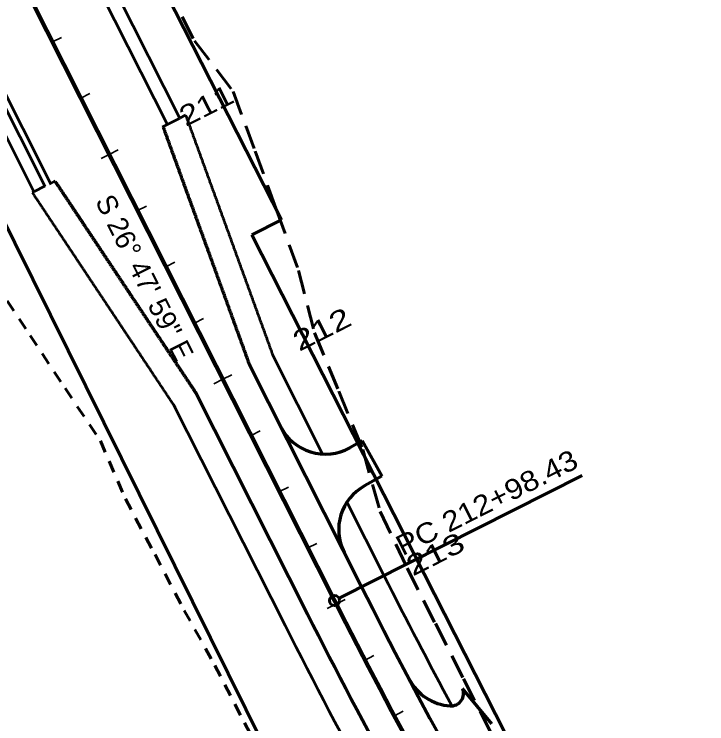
# Model space of a CAD drawing. Extents: x 2717836 to 2719883, y 337327 to 339813.
# Drawn here: x 2718519.7 to 2718794.7, y 338625.8 to 338907.4 of the extents above; entities that cross this region are included whole.
import ezdxf
from ezdxf.enums import TextEntityAlignment as Align

# ---------------------------------------------------------------- set-up
doc = ezdxf.new("R2010")
doc.units = 0
doc.header["$LTSCALE"] = 3.2
doc.linetypes.add('MEDIUM_DASHED', pattern=[4.5, 3, -1.5])
doc.linetypes.add('SHORT_DASHED', pattern=[2.7, 1.5, -1.2])
for name, color, linetype, lineweight in [('1', 7, 'Continuous', 106), ('22', 7, 'SHORT_DASHED', 60), ('23', 7, 'Continuous', 70), ('3', 7, 'Continuous', 70), ('31', 7, 'Continuous', 35), ('4', 7, 'Continuous', 53), ('6', 7, 'Continuous', 53), ('7', 7, 'Continuous', 53)]:
    doc.layers.add(name, color=color, linetype=linetype, lineweight=lineweight)

msp = doc.modelspace()

# ---------------------------------------------------------------- linework, layer by layer
at = {"layer": '1'}
msp.add_line((2718525.819, 338914.331), (2718646.872, 338674.684), dxfattribs=at)
msp.add_arc((2720744.453, 339734.238), 2350, 206.79977, 222.16044, dxfattribs=at)
at = {"layer": '22', "linetype": 'MEDIUM_DASHED'}
for p, q in [((2718579.936, 338919.199), (2718591.209, 338896.885)), ((2718591.209, 338896.885), (2718606.68, 338876.691)), ((2718606.68, 338876.691), (2718615.357, 338853.066)), ((2718615.357, 338853.066), (2718623.949, 338829.398)), ((2718623.949, 338829.398), (2718632.545, 338805.731)), ((2718632.545, 338805.731), (2718638.962, 338780.964)), ((2718638.962, 338780.964), (2718648.549, 338757.798)), ((2718648.549, 338757.798), (2718658.062, 338734.595)), ((2718658.062, 338734.595), (2718664.941, 338710.061)), ((2718664.941, 338710.061), (2718675.732, 338687.528)), ((2718675.732, 338687.528), (2718686.922, 338665.547)), ((2718686.922, 338665.547), (2718698.114, 338643.563)), ((2718698.114, 338643.563), (2718709.311, 338621.571))]:
    msp.add_line(p, q, dxfattribs=at)
at = {"layer": '22'}
for p, q in [((2718512.15, 338800.933), (2718525.967, 338779.904)), ((2718525.967, 338779.904), (2718539.924, 338758.946)), ((2718539.924, 338758.946), (2718553.951, 338738.023)), ((2718553.951, 338738.023), (2718563.831, 338715.005)), ((2718563.831, 338715.005), (2718575.588, 338692.935)), ((2718575.588, 338692.935), (2718587.141, 338670.762)), ((2718587.141, 338670.762), (2718599.4, 338648.906)), ((2718599.4, 338648.906), (2718611.069, 338626.149)), ((2718611.069, 338626.149), (2718623.203, 338603.636))]:
    msp.add_line(p, q, dxfattribs=at)
at = {"layer": '23'}
for q in [(2718555.033, 338964.813), (2718613.983, 338819.832)]:
    msp.add_line((2718625.785, 338825.842), q, dxfattribs=at)
for points in [[(2718625.836, 338603.023), (2718449.262, 338959.135), (2718424.429, 339000.578), (2718281.942, 339176.113)], [(2718753.327, 338557.168), (2718739.901, 338550.479), (2718714.737, 338599.901), (2718722.9, 338605.899), (2718678.474, 338693.162), (2718613.983, 338819.832)]]:
    msp.add_lwpolyline(points, dxfattribs=at)
at = {"layer": '3'}
for p, q in [((2718613.203, 338767.953), (2718657.583, 338680.095)), ((2718591.781, 338757.132), (2718636.161, 338669.274)), ((2718657.858, 338738.049), (2718652.963, 338735.332)), ((2718657.858, 338738.049), (2718665.624, 338724.06)), ((2718665.624, 338724.06), (2718658.816, 338720.28)), ((2718709.309, 338625.768), (2718697.745, 338639.806))]:
    msp.add_line(p, q, dxfattribs=at)
for centre, radius, start, end in [((2718643.255, 338752.818), 20, 206.79977, 299.03779), ((2718668.523, 338702.794), 20, 119.03779, 206.79977), ((2720744.453, 339734.238), 2338, 206.79977, 222.16044), ((2720744.453, 339734.238), 2362, 206.79977, 214.15238), ((2718694.161, 338652.837), 20, 207.80885, 266.07563), ((2718693.135, 338637.872), 5, 266.07563, 22.75978)]:
    msp.add_arc(centre, radius, start, end, dxfattribs=at)
for points in [[(2718578.827, 338862.622), (2718579.061, 338861.978), (2718579.291, 338861.344), (2718579.525, 338860.7), (2718579.755, 338860.066), (2718579.989, 338859.422), (2718580.219, 338858.788), (2718580.453, 338858.144), (2718580.687, 338857.5), (2718580.917, 338856.866), (2718581.151, 338856.222), (2718581.381, 338855.588), (2718581.615, 338854.944), (2718581.845, 338854.31), (2718582.079, 338853.666), (2718582.313, 338853.023), (2718582.543, 338852.388), (2718582.777, 338851.745), (2718583.007, 338851.11), (2718583.241, 338850.466), (2718583.471, 338849.832), (2718583.705, 338849.188), (2718583.935, 338848.554), (2718584.169, 338847.91), (2718584.403, 338847.267), (2718584.633, 338846.632), (2718584.867, 338845.989), (2718585.097, 338845.354), (2718585.331, 338844.71), (2718585.561, 338844.076), (2718585.795, 338843.432), (2718586.029, 338842.789), (2718586.259, 338842.154), (2718586.493, 338841.511), (2718586.723, 338840.876), (2718586.957, 338840.233), (2718587.187, 338839.598), (2718587.421, 338838.955), (2718587.655, 338838.311), (2718587.885, 338837.676), (2718588.119, 338837.033), (2718588.349, 338836.398), (2718588.583, 338835.755), (2718588.813, 338835.12), (2718589.047, 338834.477), (2718589.281, 338833.833), (2718589.511, 338833.199), (2718589.745, 338832.555), (2718589.975, 338831.92), (2718590.209, 338831.277), (2718590.439, 338830.642), (2718590.673, 338829.999), (2718590.907, 338829.355), (2718591.137, 338828.721), (2718591.371, 338828.077), (2718591.601, 338827.443), (2718591.835, 338826.799), (2718592.065, 338826.165), (2718592.299, 338825.521), (2718592.529, 338824.886), (2718592.763, 338824.243), (2718592.997, 338823.599), (2718593.227, 338822.965), (2718593.461, 338822.321), (2718593.691, 338821.687), (2718593.925, 338821.043), (2718594.155, 338820.409), (2718594.389, 338819.765), (2718594.623, 338819.122), (2718594.853, 338818.487), (2718595.087, 338817.843), (2718595.317, 338817.209), (2718595.551, 338816.565), (2718595.781, 338815.931), (2718596.015, 338815.287)], [(2718535.983, 338840.98), (2718536.362, 338840.409), (2718536.736, 338839.848), (2718537.115, 338839.278), (2718537.49, 338838.716), (2718537.868, 338838.146), (2718538.243, 338837.584), (2718538.622, 338837.014), (2718539.001, 338836.443), (2718539.375, 338835.882), (2718539.754, 338835.312), (2718540.129, 338834.75), (2718540.508, 338834.18), (2718540.882, 338833.618), (2718541.261, 338833.048), (2718541.64, 338832.477), (2718542.015, 338831.916), (2718542.394, 338831.346), (2718542.768, 338830.784), (2718543.147, 338830.214), (2718543.521, 338829.652), (2718543.9, 338829.082), (2718544.275, 338828.52), (2718544.654, 338827.95), (2718545.033, 338827.379), (2718545.407, 338826.818), (2718545.786, 338826.248), (2718546.161, 338825.686), (2718546.54, 338825.116), (2718546.914, 338824.554), (2718547.293, 338823.984), (2718547.672, 338823.413), (2718548.046, 338822.852), (2718548.425, 338822.282), (2718548.8, 338821.72), (2718549.179, 338821.15), (2718549.553, 338820.588), (2718549.932, 338820.018), (2718550.311, 338819.447), (2718550.686, 338818.886), (2718551.065, 338818.316), (2718551.439, 338817.754), (2718551.818, 338817.184), (2718552.193, 338816.622), (2718552.572, 338816.052), (2718552.95, 338815.481), (2718553.325, 338814.92), (2718553.704, 338814.349), (2718554.078, 338813.788), (2718554.457, 338813.218), (2718554.832, 338812.656), (2718555.211, 338812.086), (2718555.59, 338811.515), (2718555.964, 338810.954), (2718556.343, 338810.383), (2718556.718, 338809.822), (2718557.097, 338809.252), (2718557.471, 338808.69), (2718557.85, 338808.12), (2718558.224, 338807.558), (2718558.603, 338806.988), (2718558.982, 338806.417), (2718559.357, 338805.856), (2718559.736, 338805.286), (2718560.11, 338804.724), (2718560.489, 338804.154), (2718560.864, 338803.592), (2718561.243, 338803.022), (2718561.622, 338802.451), (2718561.996, 338801.89), (2718562.375, 338801.319), (2718562.749, 338800.758), (2718563.128, 338800.188), (2718563.503, 338799.626), (2718563.882, 338799.056)], [(2718596.015, 338815.287), (2718596.249, 338814.644), (2718596.479, 338814.009), (2718596.713, 338813.366), (2718596.943, 338812.731), (2718597.177, 338812.087), (2718597.407, 338811.453), (2718597.641, 338810.809), (2718597.875, 338810.166), (2718598.105, 338809.531), (2718598.339, 338808.888), (2718598.569, 338808.253), (2718598.803, 338807.61), (2718599.033, 338806.975), (2718599.267, 338806.332), (2718599.501, 338805.688), (2718599.731, 338805.053), (2718599.965, 338804.41), (2718600.195, 338803.775), (2718600.429, 338803.132), (2718600.659, 338802.497), (2718600.893, 338801.854), (2718601.123, 338801.219), (2718601.357, 338800.576), (2718601.591, 338799.932), (2718601.821, 338799.297), (2718602.055, 338798.654), (2718602.285, 338798.019), (2718602.519, 338797.376), (2718602.749, 338796.741), (2718602.983, 338796.098), (2718603.217, 338795.454), (2718603.447, 338794.82), (2718603.681, 338794.176), (2718603.911, 338793.542), (2718604.145, 338792.898), (2718604.375, 338792.263), (2718604.609, 338791.62), (2718604.843, 338790.976), (2718605.073, 338790.342), (2718605.307, 338789.698), (2718605.537, 338789.064), (2718605.771, 338788.42), (2718606.001, 338787.786), (2718606.235, 338787.142), (2718606.469, 338786.499), (2718606.699, 338785.864), (2718606.933, 338785.22), (2718607.163, 338784.586), (2718607.397, 338783.942), (2718607.627, 338783.308), (2718607.861, 338782.664), (2718608.095, 338782.021), (2718608.325, 338781.386), (2718608.559, 338780.743), (2718608.789, 338780.108), (2718609.023, 338779.464), (2718609.253, 338778.83), (2718609.487, 338778.186), (2718609.717, 338777.552), (2718609.951, 338776.908), (2718610.185, 338776.265), (2718610.415, 338775.63), (2718610.649, 338774.987), (2718610.879, 338774.352), (2718611.113, 338773.709), (2718611.343, 338773.074), (2718611.577, 338772.43), (2718611.811, 338771.787), (2718612.041, 338771.152), (2718612.275, 338770.509), (2718612.505, 338769.874), (2718612.739, 338769.231), (2718613.203, 338767.953)], [(2718563.882, 338799.056), (2718564.261, 338798.485), (2718564.635, 338797.924), (2718565.014, 338797.353), (2718565.389, 338796.792), (2718565.768, 338796.222), (2718566.142, 338795.66), (2718566.521, 338795.09), (2718566.9, 338794.519), (2718567.275, 338793.958), (2718567.654, 338793.387), (2718568.028, 338792.826), (2718568.407, 338792.256), (2718568.781, 338791.694), (2718569.16, 338791.124), (2718569.539, 338790.553), (2718569.914, 338789.992), (2718570.293, 338789.421), (2718570.667, 338788.86), (2718571.046, 338788.29), (2718571.421, 338787.728), (2718571.8, 338787.158), (2718572.174, 338786.596), (2718572.553, 338786.026), (2718572.932, 338785.455), (2718573.306, 338784.894), (2718573.685, 338784.323), (2718574.06, 338783.762), (2718574.439, 338783.192), (2718574.813, 338782.63), (2718575.192, 338782.06), (2718575.571, 338781.489), (2718575.946, 338780.928), (2718576.325, 338780.357), (2718576.699, 338779.796), (2718577.078, 338779.226), (2718577.453, 338778.664), (2718577.831, 338778.094), (2718578.21, 338777.523), (2718578.585, 338776.962), (2718578.964, 338776.391), (2718579.338, 338775.83), (2718579.717, 338775.26), (2718580.092, 338774.698), (2718580.471, 338774.128), (2718580.85, 338773.557), (2718581.224, 338772.996), (2718581.603, 338772.425), (2718581.978, 338771.864), (2718582.357, 338771.293), (2718582.731, 338770.732), (2718583.11, 338770.162), (2718583.489, 338769.591), (2718583.863, 338769.03), (2718584.242, 338768.459), (2718584.617, 338767.898), (2718584.996, 338767.327), (2718585.37, 338766.766), (2718585.749, 338766.196), (2718586.124, 338765.634), (2718586.503, 338765.064), (2718586.882, 338764.493), (2718587.256, 338763.932), (2718587.635, 338763.361), (2718588.009, 338762.8), (2718588.388, 338762.23), (2718588.763, 338761.668), (2718589.142, 338761.098), (2718589.521, 338760.527), (2718589.895, 338759.966), (2718590.274, 338759.395), (2718590.649, 338758.834), (2718591.028, 338758.263), (2718591.781, 338757.132)]]:
    msp.add_spline(points, degree=3, dxfattribs=at)
at = {"layer": '31'}
for p, q in [((2718534.861, 338896.43), (2718538.431, 338898.234)), ((2718546.133, 338874.116), (2718549.703, 338875.919)), ((2718557.405, 338851.801), (2718554.138, 338850.151)), ((2718557.405, 338851.801), (2718560.975, 338853.604)), ((2718568.677, 338829.486), (2718572.247, 338831.29)), ((2718579.948, 338807.171), (2718583.519, 338808.975)), ((2718591.22, 338784.857), (2718594.791, 338786.66)), ((2718602.492, 338762.542), (2718598.922, 338760.739)), ((2718602.492, 338762.542), (2718606.063, 338764.346)), ((2718613.764, 338740.227), (2718617.334, 338742.031)), ((2718625.036, 338717.913), (2718628.606, 338719.716)), ((2718636.308, 338695.598), (2718639.878, 338697.402)), ((2718647.58, 338673.284), (2718651.149, 338675.089)), ((2718647.58, 338673.284), (2718644.011, 338671.478)), ((2718658.985, 338651.037), (2718662.535, 338652.881)), ((2718670.626, 338628.913), (2718674.156, 338630.794))]:
    msp.add_line(p, q, dxfattribs=at)
at = {"layer": '31', "lineweight": 60}
msp.add_line((2718648.657, 338675.586), (2718745.197, 338724.351), dxfattribs=at)
msp.add_circle((2718646.872, 338674.684), 2, dxfattribs=at)
at = {"layer": '4'}
for p, q in [((2718580.522, 338863.702), (2718549.026, 338926.054)), ((2718502.612, 338902.608), (2718534.107, 338840.257)), ((2718578.558, 338862.711), (2718580.968, 338863.928)), ((2718533.661, 338840.032), (2718536.071, 338841.249))]:
    msp.add_line(p, q, dxfattribs=at)
at = {"layer": '6'}
for p, q in [((2718580.968, 338863.928), (2718585.431, 338866.182)), ((2718587.72, 338867.338), (2718585.431, 338866.182)), ((2718531.876, 338839.13), (2718527.413, 338836.876)), ((2718622.129, 338772.461), (2718642.139, 338732.849)), ((2718582.855, 338752.623), (2718627.235, 338664.765)), ((2718651.788, 338713.746), (2718666.509, 338684.603))]:
    msp.add_line(p, q, dxfattribs=at)
for radius, end in [(2328, 208.23606), (2372, 214.15238)]:
    msp.add_arc((2720744.453, 339734.238), radius, 206.79977, end, dxfattribs=at)
for points in [[(2718587.72, 338867.338), (2718588.461, 338865.39), (2718588.691, 338864.756), (2718588.925, 338864.112), (2718589.155, 338863.478), (2718589.389, 338862.834), (2718589.619, 338862.199), (2718589.85, 338861.564), (2718590.087, 338860.912), (2718590.317, 338860.278), (2718590.551, 338859.634), (2718590.781, 338859), (2718591.015, 338858.356), (2718591.245, 338857.722), (2718591.476, 338857.086), (2718591.713, 338856.435), (2718591.943, 338855.8), (2718592.177, 338855.156), (2718592.407, 338854.522), (2718592.641, 338853.878), (2718592.871, 338853.244), (2718593.105, 338852.6), (2718593.335, 338851.966), (2718593.566, 338851.33), (2718593.803, 338850.679), (2718594.033, 338850.044), (2718594.267, 338849.401), (2718594.497, 338848.766), (2718594.731, 338848.122), (2718594.961, 338847.488), (2718595.192, 338846.853), (2718595.429, 338846.201), (2718595.659, 338845.566), (2718595.893, 338844.923), (2718596.123, 338844.288), (2718596.357, 338843.645), (2718596.587, 338843.01), (2718596.818, 338842.375), (2718597.055, 338841.723), (2718597.285, 338841.088), (2718597.519, 338840.445), (2718597.749, 338839.81), (2718597.983, 338839.167), (2718598.213, 338838.532), (2718598.444, 338837.897), (2718598.681, 338837.245), (2718598.911, 338836.611), (2718599.145, 338835.967), (2718599.375, 338835.332), (2718599.609, 338834.689), (2718599.839, 338834.054), (2718600.07, 338833.419), (2718600.307, 338832.767), (2718600.537, 338832.133), (2718600.771, 338831.489), (2718601.001, 338830.855), (2718601.235, 338830.211), (2718601.465, 338829.576), (2718601.699, 338828.933), (2718601.929, 338828.298), (2718602.16, 338827.663), (2718602.397, 338827.011), (2718602.627, 338826.377), (2718602.861, 338825.733), (2718603.091, 338825.099), (2718603.325, 338824.455), (2718603.555, 338823.821), (2718603.786, 338823.185), (2718604.023, 338822.533), (2718604.253, 338821.899), (2718604.487, 338821.255), (2718604.717, 338820.621), (2718604.951, 338819.977), (2718605.181, 338819.343), (2718605.412, 338818.707)], [(2718526.92, 338836.627), (2718528.037, 338834.868), (2718528.412, 338834.307), (2718528.791, 338833.736), (2718529.165, 338833.175), (2718529.544, 338832.605), (2718529.919, 338832.043), (2718530.293, 338831.48), (2718530.676, 338830.902), (2718531.051, 338830.341), (2718531.43, 338829.77), (2718531.804, 338829.209), (2718532.183, 338828.639), (2718532.558, 338828.077), (2718532.932, 338827.514), (2718533.316, 338826.936), (2718533.69, 338826.375), (2718534.069, 338825.804), (2718534.444, 338825.243), (2718534.823, 338824.673), (2718535.197, 338824.111), (2718535.576, 338823.541), (2718535.95, 338822.979), (2718536.325, 338822.416), (2718536.708, 338821.838), (2718537.083, 338821.277), (2718537.462, 338820.706), (2718537.836, 338820.145), (2718538.215, 338819.575), (2718538.59, 338819.013), (2718538.964, 338818.45), (2718539.348, 338817.872), (2718539.722, 338817.311), (2718540.101, 338816.74), (2718540.475, 338816.179), (2718540.854, 338815.609), (2718541.229, 338815.047), (2718541.603, 338814.484), (2718541.987, 338813.906), (2718542.361, 338813.345), (2718542.74, 338812.774), (2718543.115, 338812.213), (2718543.494, 338811.643), (2718543.868, 338811.081), (2718544.242, 338810.518), (2718544.626, 338809.94), (2718545.001, 338809.379), (2718545.379, 338808.808), (2718545.754, 338808.247), (2718546.133, 338807.676), (2718546.507, 338807.115), (2718546.881, 338806.552), (2718547.265, 338805.974), (2718547.64, 338805.413), (2718548.019, 338804.842), (2718548.393, 338804.281), (2718548.772, 338803.71), (2718549.147, 338803.149), (2718549.526, 338802.579), (2718549.9, 338802.017), (2718550.274, 338801.454), (2718550.658, 338800.876), (2718551.032, 338800.315), (2718551.411, 338799.744), (2718551.786, 338799.183), (2718552.165, 338798.613), (2718552.539, 338798.051), (2718552.913, 338797.488), (2718553.297, 338796.91), (2718553.672, 338796.349), (2718554.051, 338795.778), (2718554.425, 338795.217), (2718554.804, 338794.646), (2718555.179, 338794.085), (2718555.553, 338793.522)], [(2718605.412, 338818.707), (2718605.649, 338818.056), (2718605.879, 338817.421), (2718606.113, 338816.778), (2718606.343, 338816.143), (2718606.577, 338815.499), (2718606.807, 338814.865), (2718607.038, 338814.23), (2718607.275, 338813.578), (2718607.505, 338812.943), (2718607.739, 338812.3), (2718607.969, 338811.665), (2718608.203, 338811.022), (2718608.433, 338810.387), (2718608.664, 338809.752), (2718608.901, 338809.1), (2718609.131, 338808.465), (2718609.365, 338807.822), (2718609.595, 338807.187), (2718609.829, 338806.544), (2718610.059, 338805.909), (2718610.293, 338805.266), (2718610.523, 338804.631), (2718610.754, 338803.996), (2718610.991, 338803.344), (2718611.221, 338802.709), (2718611.455, 338802.066), (2718611.685, 338801.431), (2718611.919, 338800.788), (2718612.149, 338800.153), (2718612.38, 338799.518), (2718612.617, 338798.866), (2718612.847, 338798.232), (2718613.081, 338797.588), (2718613.311, 338796.953), (2718613.545, 338796.31), (2718613.775, 338795.675), (2718614.006, 338795.04), (2718614.243, 338794.388), (2718614.473, 338793.754), (2718614.707, 338793.11), (2718614.937, 338792.476), (2718615.171, 338791.832), (2718615.401, 338791.198), (2718615.632, 338790.562), (2718615.869, 338789.911), (2718616.099, 338789.276), (2718616.333, 338788.632), (2718616.563, 338787.998), (2718616.797, 338787.354), (2718617.027, 338786.72), (2718617.258, 338786.084), (2718617.495, 338785.433), (2718617.725, 338784.798), (2718617.959, 338784.155), (2718618.189, 338783.52), (2718618.423, 338782.876), (2718618.653, 338782.242), (2718618.887, 338781.598), (2718619.117, 338780.964), (2718619.348, 338780.328), (2718619.585, 338779.677), (2718619.815, 338779.042), (2718620.049, 338778.399), (2718620.279, 338777.764), (2718620.513, 338777.121), (2718620.743, 338776.486), (2718620.974, 338775.851), (2718621.211, 338775.199), (2718621.441, 338774.564), (2718621.675, 338773.921), (2718621.905, 338773.286), (2718622.138, 338772.647), (2718622.603, 338771.365)], [(2718555.553, 338793.522), (2718555.936, 338792.944), (2718556.311, 338792.383), (2718556.69, 338791.812), (2718557.064, 338791.251), (2718557.443, 338790.68), (2718557.818, 338790.119), (2718558.192, 338789.556), (2718558.576, 338788.978), (2718558.95, 338788.417), (2718559.329, 338787.846), (2718559.704, 338787.285), (2718560.083, 338786.714), (2718560.457, 338786.153), (2718560.831, 338785.59), (2718561.215, 338785.012), (2718561.589, 338784.451), (2718561.968, 338783.88), (2718562.343, 338783.319), (2718562.722, 338782.748), (2718563.096, 338782.187), (2718563.475, 338781.616), (2718563.85, 338781.055), (2718564.224, 338780.492), (2718564.608, 338779.914), (2718564.982, 338779.353), (2718565.361, 338778.782), (2718565.735, 338778.221), (2718566.114, 338777.65), (2718566.489, 338777.089), (2718566.863, 338776.526), (2718567.247, 338775.948), (2718567.621, 338775.387), (2718568, 338774.816), (2718568.375, 338774.255), (2718568.754, 338773.684), (2718569.128, 338773.123), (2718569.502, 338772.56), (2718569.886, 338771.982), (2718570.261, 338771.421), (2718570.639, 338770.85), (2718571.014, 338770.289), (2718571.393, 338769.718), (2718571.767, 338769.157), (2718572.141, 338768.594), (2718572.525, 338768.016), (2718572.9, 338767.455), (2718573.279, 338766.884), (2718573.653, 338766.323), (2718574.032, 338765.752), (2718574.407, 338765.191), (2718574.781, 338764.628), (2718575.165, 338764.05), (2718575.539, 338763.489), (2718575.918, 338762.918), (2718576.292, 338762.357), (2718576.671, 338761.786), (2718577.046, 338761.225), (2718577.425, 338760.654), (2718577.799, 338760.093), (2718578.173, 338759.53), (2718578.557, 338758.952), (2718578.932, 338758.391), (2718579.311, 338757.82), (2718579.685, 338757.259), (2718580.064, 338756.688), (2718580.438, 338756.127), (2718580.813, 338755.564), (2718581.196, 338754.986), (2718581.571, 338754.425), (2718581.95, 338753.854), (2718582.324, 338753.293), (2718582.701, 338752.726), (2718583.457, 338751.591)]]:
    msp.add_spline(points, degree=3, dxfattribs=at)
at = {"layer": '7'}
for p, q in [((2718585.431, 338866.182), (2718553.935, 338928.534)), ((2718500.38, 338901.481), (2718531.876, 338839.13)), ((2718495.917, 338899.227), (2718527.413, 338836.876)), ((2718526.92, 338836.627), (2718527.413, 338836.876))]:
    msp.add_line(p, q, dxfattribs=at)

# ---------------------------------------------------------------- texts
at = {"layer": '31'}
for s, rotation, width, p in [('211', 26.8, 1.25, (2718587.771, 338862.658)), ('212', 26.8, 1.35, (2718632.858, 338773.4)), ('PC 212+98.43', 26.8, 1.15, (2718673.857, 338692.236)), ('213', 26.838, 1.35, (2718677.939, 338684.161))]:
    msp.add_text(s, height=8, rotation=rotation, dxfattribs=dict(at, width=width)).set_placement(p)
msp.add_text('S 26° 47\' 59" E', height=8, rotation=296.8, dxfattribs=at).set_placement((2718567.885, 338801.084), align=Align.CENTER)

doc.saveas('drawing.dxf')
